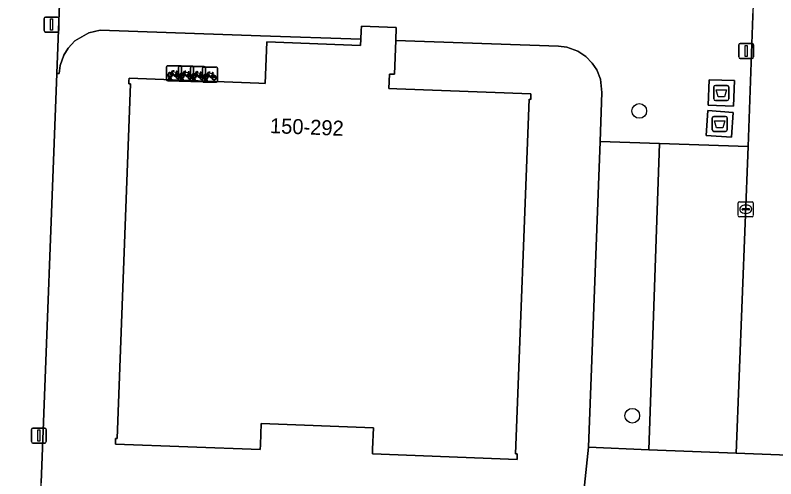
# Model space of a CAD drawing. Extents: x 160077 to 160948, y 386481 to 387498.
# Drawn here: x 160767.6 to 160818.3, y 386534.1 to 386564.9 of the extents above; entities that cross this region are included whole.
import ezdxf

# ---------------------------------------------------------------- set-up
doc = ezdxf.new("R2010")
doc.units = 0
for name, color, linetype in [('IMGEO_Afval_apart_plaats', 7, 'Continuous'), ('IMGEO_Boom', 7, 'Continuous'), ('IMGEO_Erf', 7, 'Continuous'), ('IMGEO_Fietsenrek', 7, 'Continuous'), ('IMGEO_Groenvoorziening', 7, 'Continuous'), ('IMGEO_Kolk', 7, 'Continuous'), ('IMGEO_Lichtmast', 7, 'Continuous'), ('IMGEO_Pand', 7, 'Continuous'), ('IMGEO_Pand_nummerreeks', 7, 'Continuous'), ('IMGEO_Rijbaan_lokaal_open', 7, 'Continuous'), ('IMGEO_Voetpad_gesloten', 7, 'Continuous'), ('IMGEO_Voetpad_open', 7, 'Continuous')]:
    doc.layers.add(name, color=color, linetype=linetype)

msp = doc.modelspace()

# ---------------------------------------------------------------- linework, layer by layer
at = {"layer": 'IMGEO_Afval_apart_plaats'}
for p, q in [((160814.142, 386559.37), (160814.142, 386560.17)), ((160814.142, 386560.17), (160814.142, 386559.37)), ((160814.242, 386560.27), (160815.032, 386560.27)), ((160815.032, 386560.27), (160814.242, 386560.27)), ((160815.132, 386560.17), (160815.132, 386559.37)), ((160815.132, 386559.37), (160815.132, 386560.17)), ((160815.032, 386559.27), (160814.242, 386559.27)), ((160814.242, 386559.27), (160815.032, 386559.27)), ((160814.033, 386557.308), (160814.033, 386558.108)), ((160814.033, 386558.108), (160814.033, 386557.308)), ((160814.133, 386558.208), (160814.923, 386558.208)), ((160814.923, 386558.208), (160814.133, 386558.208)), ((160815.023, 386558.108), (160815.023, 386557.308)), ((160815.023, 386557.308), (160815.023, 386558.108)), ((160814.923, 386557.208), (160814.133, 386557.208)), ((160814.133, 386557.208), (160814.923, 386557.208))]:
    msp.add_line(p, q, dxfattribs=at)
for points in [[(160814.285, 386559.984), (160814.989, 386559.984), (160814.84, 386559.514), (160814.434, 386559.514), (160814.285, 386559.984)], [(160814.176, 386557.922), (160814.88, 386557.922), (160814.731, 386557.452), (160814.325, 386557.452), (160814.176, 386557.922)]]:
    msp.add_lwpolyline(points, dxfattribs=at)
for centre, start, end in [((160814.242, 386560.17), 90, 180), ((160814.242, 386560.17), 90, 180), ((160815.032, 386560.17), 0, 90), ((160815.032, 386560.17), 360, 90), ((160814.242, 386559.37), 180, 270), ((160814.242, 386559.37), 180, 270), ((160815.032, 386559.37), 270, 0), ((160815.032, 386559.37), 270, 0), ((160814.133, 386558.108), 90, 180), ((160814.133, 386558.108), 90, 180), ((160814.923, 386558.108), 0, 90), ((160814.923, 386558.108), 360, 90), ((160814.133, 386557.308), 180, 270), ((160814.133, 386557.308), 180, 270), ((160814.923, 386557.308), 270, 0), ((160814.923, 386557.308), 270, 0)]:
    msp.add_arc(centre, 0.1, start, end, dxfattribs=at)
at = {"layer": 'IMGEO_Boom'}
for centre in [(160809.176, 386558.571), (160808.707, 386538.276)]:
    msp.add_circle(centre, 0.489, dxfattribs=at)
at = {"layer": 'IMGEO_Erf'}
msp.add_lwpolyline([(160805.389, 386532.383), (160805.793, 386536.18), (160806.574, 386556.533), (160806.689, 386559.79), (160806.581, 386560.697), (160806.34, 386561.299), (160806.043, 386561.755), (160805.616, 386562.193), (160805.082, 386562.55), (160804.342, 386562.821), (160803.796, 386562.891), (160792.956, 386563.272), (160792.867, 386561.016), (160792.537, 386561.029), (160792.5, 386560.076), (160793.032, 386560.048), (160801.963, 386559.715), (160801.952, 386559.533), (160801.948, 386559.344), (160801.841, 386559.353), (160800.933, 386535.749), (160801.048, 386535.735), (160801.041, 386535.531), (160801.041, 386535.36), (160791.399, 386535.733), (160791.411, 386536.053), (160791.467, 386537.482), (160783.999, 386537.771), (160783.943, 386536.342), (160783.931, 386536.021), (160774.288, 386536.394), (160774.291, 386536.564), (160774.294, 386536.759), (160774.404, 386536.759), (160775.29, 386560.372), (160775.18, 386560.377), (160775.189, 386560.573), (160775.197, 386560.752), (160783.837, 386560.413), (160784.271, 386560.396), (160784.38, 386563.172), (160790.62, 386562.926), (160790.637, 386563.354), (160783.962, 386563.58), (160773.275, 386563.942), (160772.52, 386563.775), (160771.595, 386563.239), (160771.143, 386562.759), (160770.85, 386562.285), (160770.606, 386561.588), (160770.54, 386561.067), (160770.395, 386561.072), (160769.354, 386533.814)], dxfattribs=at)
at = {"layer": 'IMGEO_Fietsenrek'}
for p, q in [((160777.694, 386560.661), (160777.694, 386561.502)), ((160777.694, 386561.502), (160777.694, 386560.661)), ((160777.769, 386561.586), (160778.61, 386561.586)), ((160778.61, 386561.586), (160777.769, 386561.586)), ((160778.493, 386560.63), (160778.493, 386561.471)), ((160778.493, 386561.471), (160778.493, 386560.63)), ((160778.568, 386561.555), (160779.409, 386561.555)), ((160779.409, 386561.555), (160778.568, 386561.555)), ((160778.694, 386561.511), (160778.694, 386560.67)), ((160778.694, 386560.67), (160778.694, 386561.511)), ((160779.293, 386560.598), (160779.293, 386561.439)), ((160779.293, 386561.439), (160779.293, 386560.598)), ((160779.368, 386561.523), (160780.209, 386561.523)), ((160780.209, 386561.523), (160779.368, 386561.523)), ((160779.493, 386561.48), (160779.493, 386560.639)), ((160779.493, 386560.639), (160779.493, 386561.48)), ((160780.092, 386560.567), (160780.092, 386561.408)), ((160780.092, 386561.408), (160780.092, 386560.567)), ((160780.167, 386561.492), (160781.008, 386561.492)), ((160781.008, 386561.492), (160780.167, 386561.492)), ((160780.293, 386561.448), (160780.293, 386560.607)), ((160780.293, 386560.607), (160780.293, 386561.448)), ((160781.092, 386561.417), (160781.092, 386560.576)), ((160781.092, 386560.576), (160781.092, 386561.417)), ((160777.963, 386560.853), (160777.964, 386560.846)), ((160778.381, 386561.135), (160778.417, 386561.04)), ((160779.18, 386561.104), (160779.216, 386561.009)), ((160779.98, 386561.072), (160780.016, 386560.977)), ((160780.779, 386561.041), (160780.815, 386560.946)), ((160778.619, 386560.586), (160777.778, 386560.586)), ((160777.778, 386560.586), (160778.619, 386560.586)), ((160777.821, 386560.67), (160777.86, 386560.83)), ((160777.855, 386560.67), (160777.821, 386560.67)), ((160777.89, 386560.818), (160777.855, 386560.67)), ((160777.932, 386560.842), (160777.931, 386560.846)), ((160777.973, 386560.67), (160777.939, 386560.812)), ((160777.971, 386560.816), (160778.006, 386560.67)), ((160778.006, 386560.67), (160777.973, 386560.67)), ((160779.418, 386560.555), (160778.577, 386560.555)), ((160778.577, 386560.555), (160779.418, 386560.555)), ((160778.62, 386560.639), (160778.659, 386560.799)), ((160778.654, 386560.639), (160778.62, 386560.639)), ((160778.689, 386560.787), (160778.654, 386560.639)), ((160778.731, 386560.811), (160778.73, 386560.815)), ((160778.772, 386560.639), (160778.738, 386560.781)), ((160778.762, 386560.822), (160778.763, 386560.815)), ((160778.77, 386560.785), (160778.805, 386560.639)), ((160778.805, 386560.639), (160778.772, 386560.639)), ((160780.218, 386560.523), (160779.377, 386560.523)), ((160779.377, 386560.523), (160780.218, 386560.523)), ((160779.42, 386560.607), (160779.459, 386560.767)), ((160779.454, 386560.607), (160779.42, 386560.607)), ((160779.489, 386560.755), (160779.454, 386560.607)), ((160779.531, 386560.779), (160779.53, 386560.783)), ((160779.572, 386560.607), (160779.538, 386560.749)), ((160779.562, 386560.79), (160779.563, 386560.783)), ((160779.57, 386560.753), (160779.605, 386560.607)), ((160779.605, 386560.607), (160779.572, 386560.607)), ((160781.017, 386560.492), (160780.176, 386560.492)), ((160780.176, 386560.492), (160781.017, 386560.492)), ((160780.219, 386560.576), (160780.258, 386560.736)), ((160780.253, 386560.576), (160780.219, 386560.576)), ((160780.288, 386560.724), (160780.253, 386560.576)), ((160780.33, 386560.748), (160780.329, 386560.752)), ((160780.371, 386560.576), (160780.337, 386560.718)), ((160780.361, 386560.759), (160780.362, 386560.752)), ((160780.369, 386560.722), (160780.404, 386560.576)), ((160780.404, 386560.576), (160780.371, 386560.576))]:
    msp.add_line(p, q, dxfattribs=at)
for points in [[(160778.028, 386561.06), (160777.976, 386560.97), (160777.936, 386560.945), (160777.937, 386560.992), (160777.992, 386561.086)], [(160778.007, 386561.112), (160778.102, 386561.276), (160778.188, 386561.262), (160778.19, 386561.253), (160778.134, 386561.242), (160778.107, 386561.197), (160778.363, 386561.156)], [(160778.303, 386560.868), (160778.253, 386560.868), (160778.062, 386561.119), (160778.043, 386561.087)], [(160778.35, 386561.131), (160778.093, 386561.172), (160778.076, 386561.143), (160778.243, 386560.923), (160778.35, 386561.131)], [(160778.398, 386561.033), (160778.368, 386561.11), (160778.259, 386560.892), (160778.302, 386560.892)], [(160778.332, 386560.892), (160778.452, 386560.891), (160778.408, 386561.005)], [(160778.428, 386561.012), (160778.483, 386560.867), (160778.333, 386560.867)], [(160778.363, 386561.156), (160778.388, 386561.205), (160778.382, 386561.209), (160778.359, 386561.213), (160778.347, 386561.22), (160778.346, 386561.223), (160778.348, 386561.228), (160778.443, 386561.213), (160778.445, 386561.203), (160778.435, 386561.19), (160778.423, 386561.184), (160778.409, 386561.19), (160778.381, 386561.135)], [(160778.827, 386561.029), (160778.775, 386560.939), (160778.735, 386560.914), (160778.736, 386560.961), (160778.791, 386561.055)], [(160778.806, 386561.081), (160778.901, 386561.245), (160778.987, 386561.231), (160778.989, 386561.222), (160778.933, 386561.211), (160778.906, 386561.166), (160779.162, 386561.125)], [(160779.102, 386560.837), (160779.052, 386560.837), (160778.861, 386561.088), (160778.842, 386561.056)], [(160779.149, 386561.1), (160778.892, 386561.141), (160778.875, 386561.112), (160779.042, 386560.892), (160779.149, 386561.1)], [(160779.197, 386561.002), (160779.167, 386561.079), (160779.058, 386560.861), (160779.101, 386560.861)], [(160779.131, 386560.861), (160779.251, 386560.86), (160779.207, 386560.974)], [(160779.227, 386560.981), (160779.282, 386560.836), (160779.132, 386560.836)], [(160779.162, 386561.125), (160779.187, 386561.174), (160779.181, 386561.178), (160779.158, 386561.182), (160779.146, 386561.189), (160779.145, 386561.192), (160779.147, 386561.197), (160779.242, 386561.182), (160779.244, 386561.172), (160779.234, 386561.159), (160779.222, 386561.153), (160779.208, 386561.159), (160779.18, 386561.104)], [(160779.627, 386560.997), (160779.575, 386560.907), (160779.535, 386560.882), (160779.536, 386560.929), (160779.591, 386561.023)], [(160779.606, 386561.049), (160779.701, 386561.213), (160779.787, 386561.199), (160779.789, 386561.19), (160779.733, 386561.179), (160779.706, 386561.134), (160779.962, 386561.093)], [(160779.902, 386560.805), (160779.852, 386560.805), (160779.661, 386561.056), (160779.642, 386561.024)], [(160779.949, 386561.068), (160779.692, 386561.109), (160779.675, 386561.08), (160779.842, 386560.86), (160779.949, 386561.068)], [(160779.997, 386560.97), (160779.967, 386561.047), (160779.858, 386560.829), (160779.901, 386560.829)], [(160779.931, 386560.829), (160780.051, 386560.828), (160780.007, 386560.942)], [(160780.027, 386560.949), (160780.082, 386560.804), (160779.932, 386560.804)], [(160779.962, 386561.093), (160779.987, 386561.142), (160779.981, 386561.146), (160779.958, 386561.15), (160779.946, 386561.157), (160779.945, 386561.16), (160779.947, 386561.165), (160780.042, 386561.15), (160780.044, 386561.14), (160780.034, 386561.127), (160780.022, 386561.121), (160780.008, 386561.127), (160779.98, 386561.072)], [(160780.426, 386560.966), (160780.374, 386560.876), (160780.334, 386560.851), (160780.335, 386560.898), (160780.39, 386560.992)], [(160780.405, 386561.018), (160780.5, 386561.182), (160780.586, 386561.168), (160780.588, 386561.159), (160780.532, 386561.148), (160780.505, 386561.103), (160780.761, 386561.062)], [(160780.701, 386560.774), (160780.651, 386560.774), (160780.46, 386561.025), (160780.441, 386560.993)], [(160780.748, 386561.037), (160780.491, 386561.078), (160780.474, 386561.049), (160780.641, 386560.829), (160780.748, 386561.037)], [(160780.796, 386560.939), (160780.766, 386561.016), (160780.657, 386560.798), (160780.7, 386560.798)], [(160780.73, 386560.798), (160780.85, 386560.797), (160780.806, 386560.911)], [(160780.826, 386560.918), (160780.881, 386560.773), (160780.731, 386560.773)], [(160780.761, 386561.062), (160780.786, 386561.111), (160780.78, 386561.115), (160780.757, 386561.119), (160780.745, 386561.126), (160780.744, 386561.129), (160780.746, 386561.134), (160780.841, 386561.119), (160780.843, 386561.109), (160780.833, 386561.096), (160780.821, 386561.09), (160780.807, 386561.096), (160780.779, 386561.041)]]:
    msp.add_lwpolyline(points, dxfattribs=at)
for centre, radius, start, end in [((160777.772, 386561.508), 0.0779, 92.4484, 184.2845), ((160777.772, 386561.508), 0.0779, 92.4484, 184.2845), ((160778.571, 386561.477), 0.0779, 92.4484, 184.2845), ((160778.571, 386561.477), 0.0779, 92.4484, 184.2845), ((160778.616, 386561.508), 0.0779, 2.4484, 94.2845), ((160778.616, 386561.508), 0.0779, 2.4484, 94.2845), ((160779.371, 386561.445), 0.0779, 92.4484, 184.2845), ((160779.371, 386561.445), 0.0779, 92.4484, 184.2845), ((160779.415, 386561.477), 0.0779, 2.4484, 94.2845), ((160779.415, 386561.477), 0.0779, 2.4484, 94.2845), ((160780.17, 386561.414), 0.0779, 92.4484, 184.2845), ((160780.17, 386561.414), 0.0779, 92.4484, 184.2845), ((160780.215, 386561.445), 0.0779, 2.4484, 94.2845), ((160780.215, 386561.445), 0.0779, 2.4484, 94.2845), ((160781.014, 386561.414), 0.0779, 2.4484, 94.2845), ((160781.014, 386561.414), 0.0779, 2.4484, 94.2845), ((160777.934, 386560.971), 0.159, 62.6766, 242.1369), ((160777.934, 386560.971), 0.129, 63.3192, 238.903), ((160777.914, 386560.842), 0.0499, 12.8025, 158.6934), ((160777.914, 386560.842), 0.0174, 12.8025, 163.4502), ((160777.934, 386560.971), 0.129, 283.6043, 43.4302), ((160777.934, 386560.971), 0.159, 283.5766, 46.6042), ((160778.461, 386560.887), 0.159, 113.3408, 178.3217), ((160778.461, 386560.887), 0.159, 187.0065, 105.7708), ((160778.461, 386560.887), 0.129, 113.923, 177.9556), ((160778.461, 386560.887), 0.129, 188.6715, 104.5883), ((160778.733, 386560.94), 0.159, 62.6766, 242.1369), ((160778.733, 386560.94), 0.129, 63.3192, 238.903), ((160778.713, 386560.811), 0.0499, 12.8025, 158.6934), ((160778.733, 386560.94), 0.129, 283.6043, 43.4302), ((160778.733, 386560.94), 0.159, 283.5766, 46.6042), ((160779.26, 386560.856), 0.159, 113.3408, 178.3217), ((160779.26, 386560.856), 0.159, 187.0065, 105.7708), ((160779.26, 386560.856), 0.129, 113.923, 177.9556), ((160779.26, 386560.856), 0.129, 188.6715, 104.5883), ((160779.533, 386560.908), 0.159, 62.6766, 242.1369), ((160779.533, 386560.908), 0.129, 63.3192, 238.903), ((160779.533, 386560.908), 0.129, 283.6043, 43.4302), ((160779.533, 386560.908), 0.159, 283.5766, 46.6042), ((160780.06, 386560.824), 0.159, 113.3408, 178.3217), ((160780.06, 386560.824), 0.159, 187.0065, 105.7708), ((160780.06, 386560.824), 0.129, 113.923, 177.9556), ((160780.06, 386560.824), 0.129, 188.6715, 104.5883), ((160780.332, 386560.877), 0.159, 62.6766, 242.1369), ((160780.332, 386560.877), 0.129, 63.3192, 238.903), ((160780.332, 386560.877), 0.129, 283.6043, 43.4302), ((160780.332, 386560.877), 0.159, 283.5766, 46.6042), ((160780.859, 386560.793), 0.159, 113.3408, 178.3217), ((160780.859, 386560.793), 0.159, 187.0065, 105.7708), ((160780.859, 386560.793), 0.129, 113.923, 177.9556), ((160780.859, 386560.793), 0.129, 188.6715, 104.5883), ((160777.772, 386560.664), 0.0779, 182.4484, 274.2845), ((160777.772, 386560.664), 0.0779, 182.4484, 274.2845), ((160777.934, 386560.971), 0.159, 253.9967, 271.7867), ((160777.934, 386560.971), 0.129, 253.415, 269.0204), ((160778.571, 386560.633), 0.0779, 182.4484, 274.2845), ((160778.571, 386560.633), 0.0779, 182.4484, 274.2845), ((160778.616, 386560.664), 0.0779, 272.4484, 4.2845), ((160778.616, 386560.664), 0.0779, 272.4484, 4.2845), ((160778.733, 386560.94), 0.159, 253.9967, 271.7867), ((160778.713, 386560.811), 0.0174, 12.8025, 163.4502), ((160778.733, 386560.94), 0.129, 253.415, 269.0204), ((160779.371, 386560.601), 0.0779, 182.4484, 274.2845), ((160779.371, 386560.601), 0.0779, 182.4484, 274.2845), ((160779.415, 386560.633), 0.0779, 272.4484, 4.2845), ((160779.415, 386560.633), 0.0779, 272.4484, 4.2845), ((160779.513, 386560.779), 0.0499, 12.8025, 158.6934), ((160779.533, 386560.908), 0.159, 253.9967, 271.7867), ((160779.513, 386560.779), 0.0174, 12.8025, 163.4502), ((160779.533, 386560.908), 0.129, 253.415, 269.0204), ((160780.17, 386560.57), 0.0779, 182.4484, 274.2845), ((160780.17, 386560.57), 0.0779, 182.4484, 274.2845), ((160780.215, 386560.601), 0.0779, 272.4484, 4.2845), ((160780.215, 386560.601), 0.0779, 272.4484, 4.2845), ((160780.312, 386560.748), 0.0499, 12.8025, 158.6934), ((160780.332, 386560.877), 0.159, 253.9967, 271.7867), ((160780.312, 386560.748), 0.0174, 12.8025, 163.4502), ((160780.332, 386560.877), 0.129, 253.415, 269.0204), ((160781.014, 386560.57), 0.0779, 272.4484, 4.2845), ((160781.014, 386560.57), 0.0779, 272.4484, 4.2845)]:
    msp.add_arc(centre, radius, start, end, dxfattribs=at)
at = {"layer": 'IMGEO_Groenvoorziening'}
for points in [[(160809.8, 386536.015), (160810.528, 386556.399), (160806.574, 386556.533), (160805.793, 386536.18)], [(160815.636, 386535.774), (160816.415, 386556.199), (160810.528, 386556.399), (160809.8, 386536.015)]]:
    msp.add_lwpolyline(points, close=True, dxfattribs=at)
at = {"layer": 'IMGEO_Kolk'}
for p, q in [((160815.764, 386551.599), (160815.764, 386552.451)), ((160815.839, 386552.525), (160816.691, 386552.525)), ((160816.252, 386552.305), (160816.277, 386552.305)), ((160816.765, 386552.451), (160816.765, 386551.599)), ((160816.023, 386552.019), (160816.023, 386552.031)), ((160816.461, 386551.982), (160816.063, 386551.982)), ((160816.066, 386552.068), (160816.464, 386552.068)), ((160816.275, 386551.745), (160816.25, 386551.745)), ((160816.507, 386552.031), (160816.507, 386552.019)), ((160816.691, 386551.525), (160815.839, 386551.525))]:
    msp.add_line(p, q, dxfattribs=at)
for points in [[(160815.764, 386551.599), (160815.764, 386552.451)], [(160815.839, 386552.525), (160816.691, 386552.525)], [(160816.765, 386552.451), (160816.765, 386551.599)], [(160816.691, 386551.525), (160815.839, 386551.525)]]:
    msp.add_lwpolyline(points, dxfattribs=at)
for centre, radius, start, end in [((160815.841, 386552.449), 0.0765, 91.552, 178.448), ((160815.841, 386552.449), 0.0765, 91.552, 178.448), ((160816.689, 386552.449), 0.0765, 1.552, 88.448), ((160816.689, 386552.449), 0.0765, 1.552, 88.448), ((160816.063, 386552.028), 0.0403, 85.8775, 175.7526), ((160816.06, 386552.018), 0.0366, 178.938, 274.7102), ((160816.464, 386552.025), 0.043, 264.8664, 352.4533), ((160816.468, 386552.03), 0.0386, 1.7309, 96.639), ((160815.841, 386551.601), 0.0765, 181.552, 268.448), ((160815.841, 386551.601), 0.0765, 181.552, 268.448), ((160816.689, 386551.601), 0.0765, 271.552, 358.448), ((160816.689, 386551.601), 0.0765, 271.552, 358.448)]:
    msp.add_arc(centre, radius, start, end, dxfattribs=at)
for centre, major_axis, ratio, start_param, end_param in [((160816.251, 386552.025), (-0.387, 0.002), 0.722429, 4.712389, 7.853982), ((160816.276, 386552.025), (-0.39, 0.002), 0.717154, 1.570796, 4.712389)]:
    msp.add_ellipse(centre, major_axis=major_axis, ratio=ratio, start_param=start_param, end_param=end_param, dxfattribs=at)
at = {"layer": 'IMGEO_Lichtmast'}
for p, q in [((160769.539, 386563.925), (160769.539, 386564.725)), ((160769.539, 386564.725), (160769.539, 386563.925)), ((160769.639, 386564.825), (160770.429, 386564.825)), ((160770.429, 386564.825), (160769.639, 386564.825)), ((160770.529, 386564.725), (160770.529, 386563.925)), ((160770.529, 386563.925), (160770.529, 386564.725)), ((160770.429, 386563.825), (160769.639, 386563.825)), ((160769.639, 386563.825), (160770.429, 386563.825)), ((160815.798, 386562.165), (160815.798, 386562.965)), ((160815.798, 386562.965), (160815.798, 386562.165)), ((160815.898, 386563.065), (160816.688, 386563.065)), ((160816.688, 386563.065), (160815.898, 386563.065)), ((160816.788, 386562.965), (160816.788, 386562.165)), ((160816.788, 386562.165), (160816.788, 386562.965)), ((160816.688, 386562.065), (160815.898, 386562.065)), ((160815.898, 386562.065), (160816.688, 386562.065)), ((160768.697, 386536.554), (160768.697, 386537.354)), ((160768.697, 386537.354), (160768.697, 386536.554)), ((160768.797, 386537.454), (160769.587, 386537.454)), ((160769.587, 386537.454), (160768.797, 386537.454)), ((160769.687, 386537.354), (160769.687, 386536.554)), ((160769.687, 386536.554), (160769.687, 386537.354)), ((160769.587, 386536.454), (160768.797, 386536.454)), ((160768.797, 386536.454), (160769.587, 386536.454))]:
    msp.add_line(p, q, dxfattribs=at)
for points in [[(160769.959, 386564.7), (160770.109, 386564.7), (160770.109, 386563.95), (160769.959, 386563.95), (160769.959, 386564.7)], [(160816.218, 386562.94), (160816.368, 386562.94), (160816.368, 386562.19), (160816.218, 386562.19), (160816.218, 386562.94)], [(160769.117, 386537.329), (160769.267, 386537.329), (160769.267, 386536.579), (160769.117, 386536.579), (160769.117, 386537.329)]]:
    msp.add_lwpolyline(points, dxfattribs=at)
for centre, start, end in [((160769.639, 386564.725), 90, 180), ((160769.639, 386564.725), 90, 180), ((160770.429, 386564.725), 0, 90), ((160770.429, 386564.725), 360, 90), ((160769.639, 386563.925), 180, 270), ((160769.639, 386563.925), 180, 270), ((160770.429, 386563.925), 270, 0), ((160770.429, 386563.925), 270, 0), ((160815.898, 386562.965), 90, 180), ((160815.898, 386562.965), 90, 180), ((160816.688, 386562.965), 0, 90), ((160816.688, 386562.965), 360, 90), ((160815.898, 386562.165), 180, 270), ((160815.898, 386562.165), 180, 270), ((160816.688, 386562.165), 270, 0), ((160816.688, 386562.165), 270, 0), ((160768.797, 386537.354), 90, 180), ((160768.797, 386537.354), 90, 180), ((160769.587, 386537.354), 0, 90), ((160769.587, 386537.354), 360, 90), ((160768.797, 386536.554), 180, 270), ((160768.797, 386536.554), 180, 270), ((160769.587, 386536.554), 270, 0), ((160769.587, 386536.554), 270, 0)]:
    msp.add_arc(centre, 0.1, start, end, dxfattribs=at)
at = {"layer": 'IMGEO_Pand'}
msp.add_lwpolyline([(160775.197, 386560.752), (160775.189, 386560.573), (160775.18, 386560.377), (160775.29, 386560.372), (160774.404, 386536.759), (160774.294, 386536.759), (160774.291, 386536.564), (160774.288, 386536.394), (160783.931, 386536.021), (160783.943, 386536.342), (160783.999, 386537.771), (160791.467, 386537.482), (160791.411, 386536.053), (160791.399, 386535.733), (160801.041, 386535.36), (160801.041, 386535.531), (160801.048, 386535.735), (160800.933, 386535.749), (160801.841, 386559.353), (160801.948, 386559.344), (160801.952, 386559.533), (160801.963, 386559.715), (160793.032, 386560.048), (160792.5, 386560.076), (160792.537, 386561.029), (160792.867, 386561.016), (160792.956, 386563.272), (160792.989, 386564.124), (160790.671, 386564.215), (160790.659, 386563.906), (160790.637, 386563.354), (160790.62, 386562.926), (160784.38, 386563.172), (160784.271, 386560.396), (160783.837, 386560.413)], close=True, dxfattribs=at)
at = {"layer": 'IMGEO_Rijbaan_lokaal_open'}
msp.add_lwpolyline([(160822.067, 386598.193), (160817.876, 386598.837), (160817.831, 386596.63), (160816.725, 386565.069), (160816.73, 386564.895), (160816.415, 386556.199), (160815.636, 386535.774), (160851.542, 386534.405)], dxfattribs=at)
at = {"layer": 'IMGEO_Voetpad_gesloten'}
for points in [[(160815.51, 386560.589), (160813.817, 386560.641), (160813.765, 386558.951), (160815.458, 386558.899)], [(160815.431, 386558.471), (160813.741, 386558.591), (160813.624, 386556.944), (160815.314, 386556.824)]]:
    msp.add_lwpolyline(points, close=True, dxfattribs=at)
at = {"layer": 'IMGEO_Voetpad_open'}
for points in [[(160765.063, 386501.74), (160768.147, 386501.867), (160768.18, 386503.769), (160768.603, 386514.582), (160768.792, 386519.432), (160769.344, 386533.556), (160769.354, 386533.814), (160770.395, 386561.072), (160770.652, 386568.032), (160767.902, 386568.148), (160767.538, 386568.163)], [(160770.652, 386568.032), (160770.395, 386561.072), (160770.54, 386561.067), (160770.606, 386561.588), (160770.85, 386562.285), (160771.143, 386562.759), (160771.595, 386563.239), (160772.52, 386563.775), (160773.275, 386563.942), (160783.962, 386563.58), (160790.637, 386563.354), (160790.659, 386563.906), (160790.671, 386564.215), (160792.989, 386564.124), (160792.956, 386563.272), (160803.796, 386562.891), (160804.342, 386562.821), (160805.082, 386562.55), (160805.616, 386562.193), (160806.043, 386561.755), (160806.34, 386561.299), (160806.581, 386560.697), (160806.689, 386559.79), (160806.574, 386556.533), (160810.528, 386556.399), (160816.415, 386556.199), (160816.73, 386564.895), (160816.725, 386565.069)], [(160853.105, 386534.345), (160851.542, 386534.405), (160815.636, 386535.774), (160809.8, 386536.015), (160805.793, 386536.18), (160805.389, 386532.383), (160851.393, 386530.511), (160883.212, 386529.228)]]:
    msp.add_lwpolyline(points, dxfattribs=at)
for points in [[(160815.458, 386558.899), (160813.765, 386558.951), (160813.817, 386560.641), (160815.51, 386560.589)], [(160815.314, 386556.824), (160813.624, 386556.944), (160813.741, 386558.591), (160815.431, 386558.471)]]:
    msp.add_lwpolyline(points, close=True, dxfattribs=at)

# ---------------------------------------------------------------- texts
at = {"layer": 'IMGEO_Pand_nummerreeks'}
msp.add_text('150-292', height=1, rotation=357.7731, dxfattribs=at).set_placement((160784.57, 386557.101))

doc.saveas('drawing.dxf')
